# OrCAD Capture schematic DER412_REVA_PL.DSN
size C; title: 120V / 100mA    A19 application; rev: A; note: <Doc>
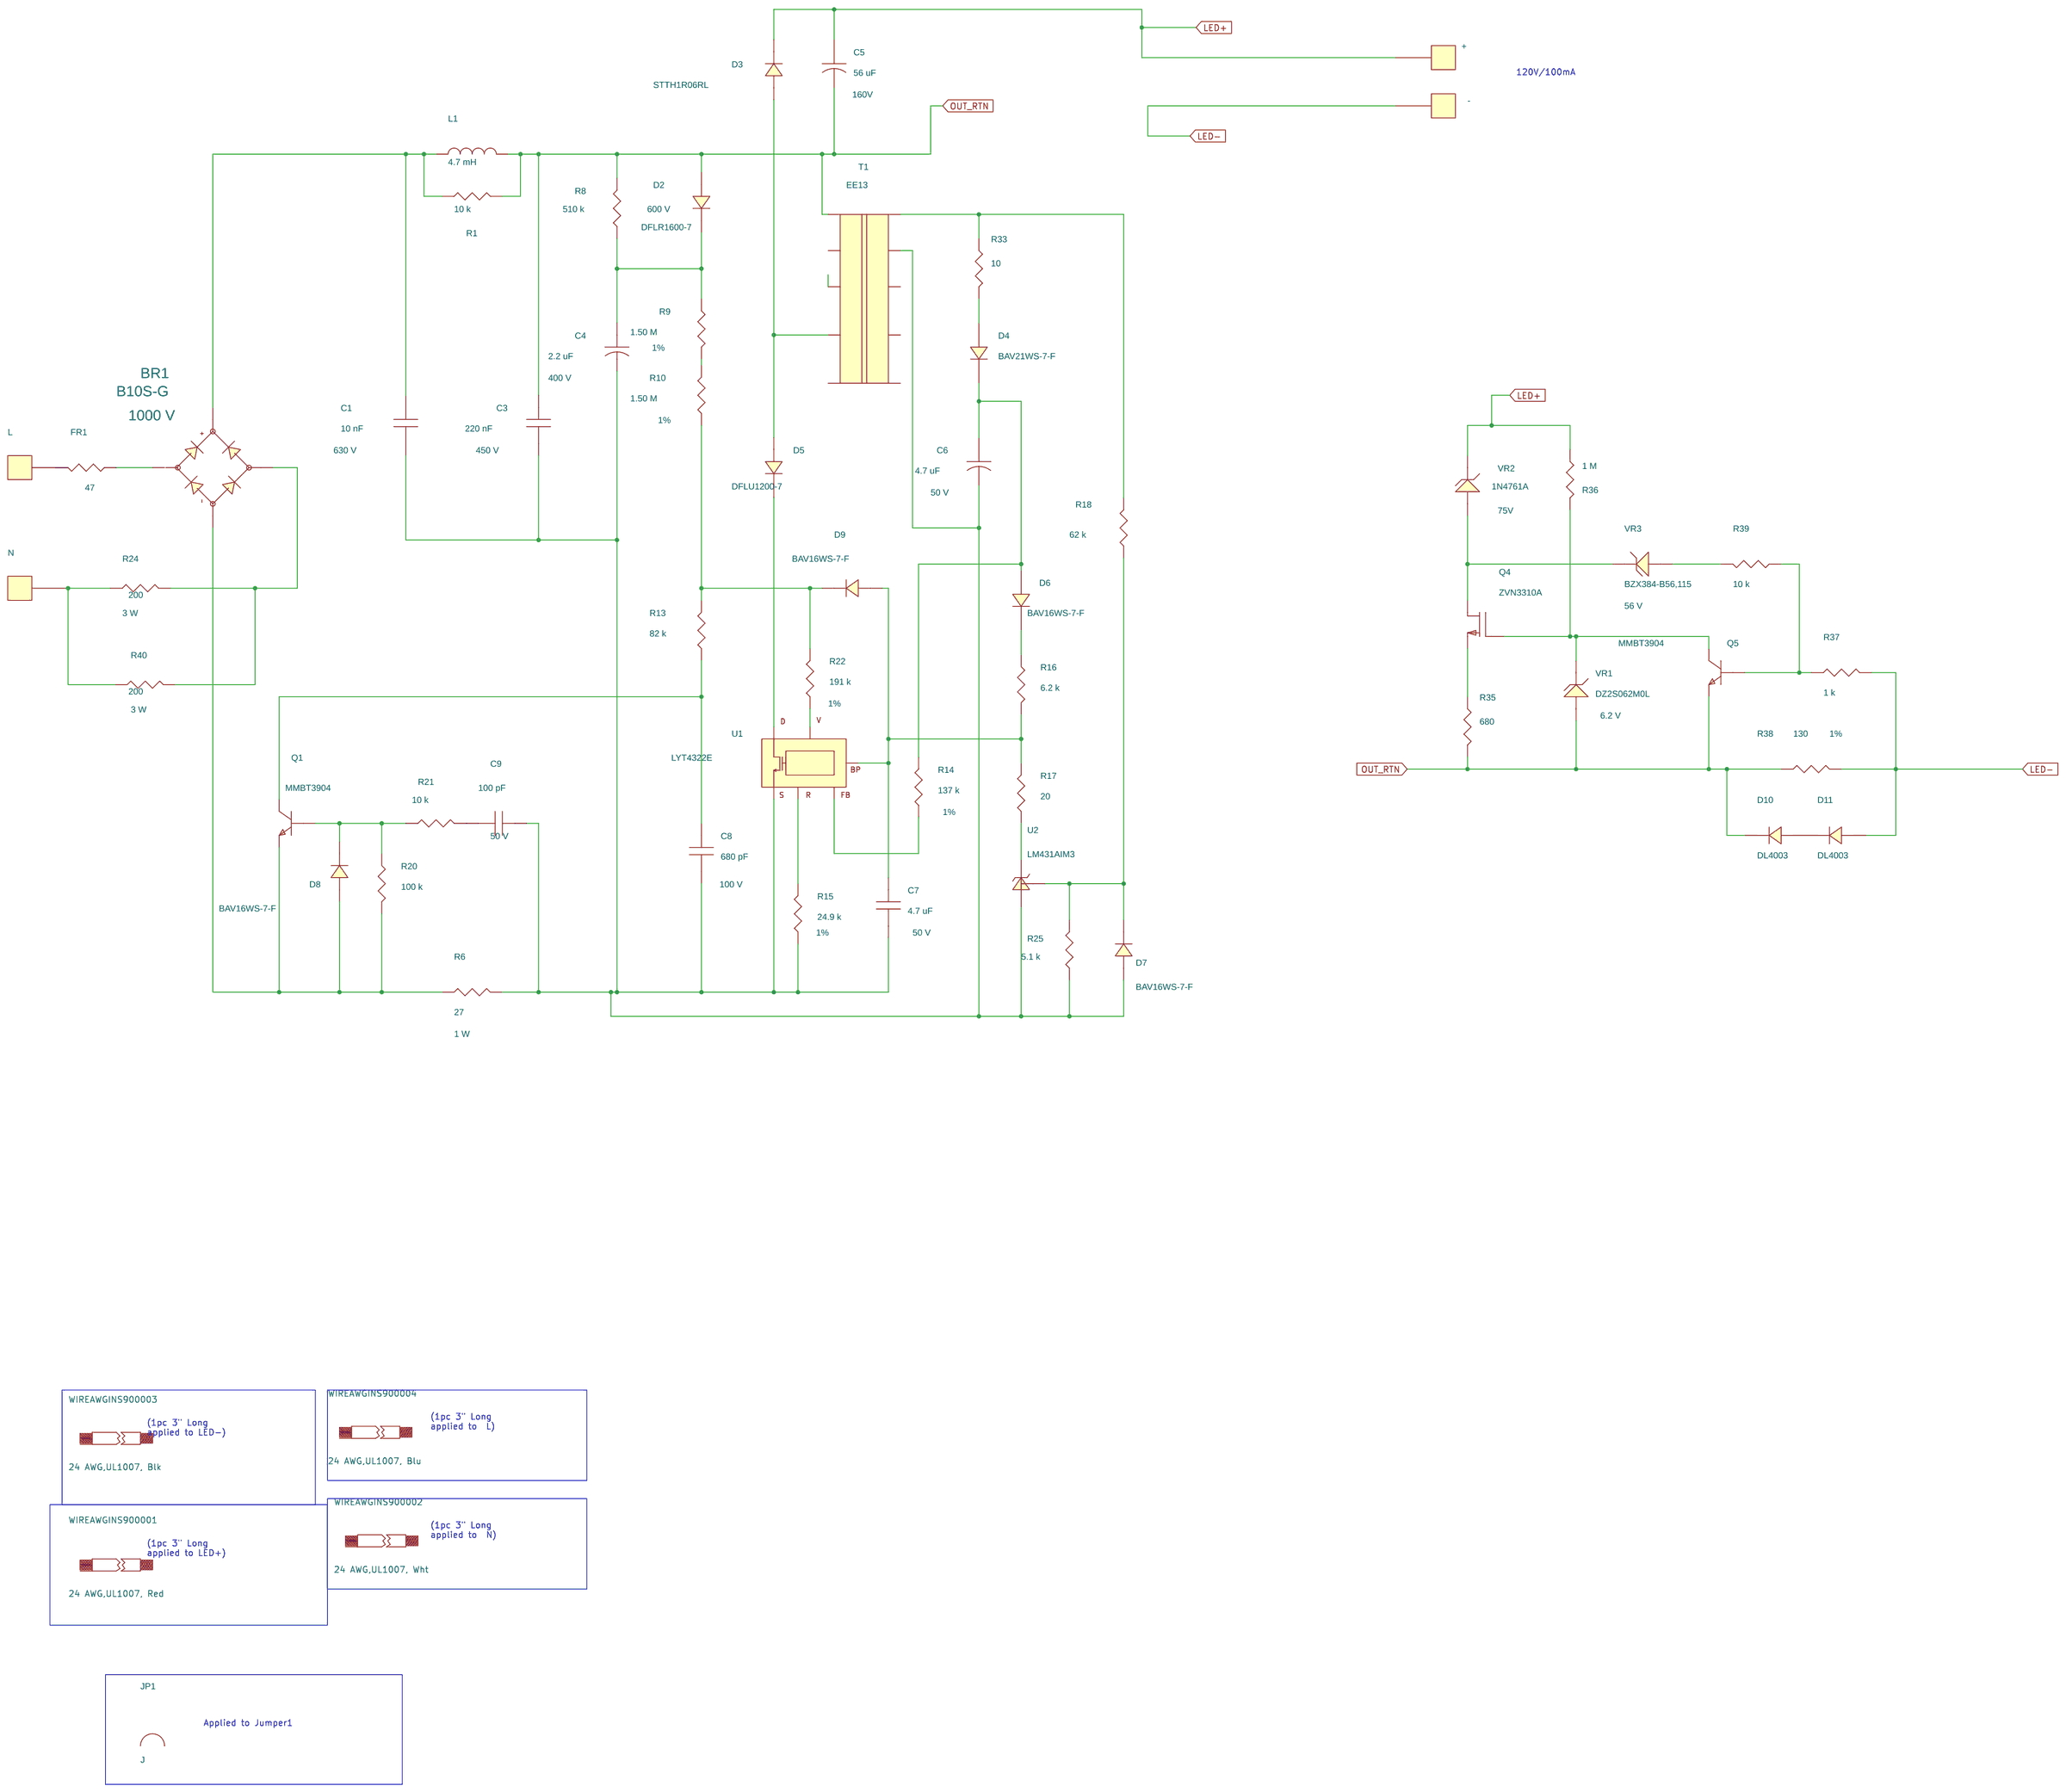
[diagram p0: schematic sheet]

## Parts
+  PCB Terminal 22 AWG  [pi_hole_22awg]
-  PCB Terminal 22 AWG  [pi_hole_22awg]
BR1  B10S-G  [pismsoic4]
C1  10 nF  [pinpcaprad500x200400030]
C3  220 nF  [pi_np_cap_rad470x220ls400d40]
C4  2.2 uF  [pipolcapcyld250ls100030]
C5  56 uF  [pipolcapcyld400ls200040800h]
C6  4.7 uF  [pipolcapclyd200ls80030]
C7  4.7 uF  [pismc0805]
C8  680 pF  [pismc0603]
C9  100 pF  [pismc0603]
D2  DFLR1600-7  [pismddflr120012]
D3  STTH1R06RL  [pidv200x110x040do41]
D4  BAV21WS-7-F  [pismsod323]
D5  DFLU1200-7  [pismddflr120012]
D6  BAV16WS-7-F  [pismsod323]
D7  BAV16WS-7-F  [pismsod323]
D8  BAV16WS-7-F  [pismsod323]
D9  BAV16WS-7-F  [pismsod323]
D10  DL4003  [pismdmll4112]
D11  DL4003  [pismdmll4112]
FR1  47  [PI_2W_VRES240LS200D040]
JP1  J  [pi_jumper400]
L  PCB Terminal 22 AWG  [pi_hole_22awg]
L1  4.7 mH  [pi12wvresd180ls150d040]
N  PCB Terminal 22 AWG  [pi_hole_22awg]
Q1  MMBT3904  [pismsot23132]
Q4  ZVN3310A  [PITO92R100]
Q5  MMBT3904  [pismsot23132]
R1  10 k  [pismr0805]
R6  27  [pi1wresd200ls725d040]
R8  510 k  [pismr1206]
R9  1.50 M  [pismr1206]
R10  1.50 M  [pismr1206]
R13  82 k  [pismr0603]
R14  137 k  [pismr0805]
R15  24.9 k  [pismr0805]
R16  6.2 k  [pismr0805]
R17  20  [pismr1206]
R18  62 k  [pismr0805]
R20  100 k  [pismr0603]
R21  10 k  [pismr0603]
R22  191 k  [pismr0603]
R24  200  [pi2wresd200ls725d040]
R25  5.1 k  [pismr0805]
R33  10  [pismr0805]
R35  680  [pismr0603]
R36  1 M  [pi14wresd100ls400d030]
R37  1 k  [pismr0805]
R38  130  [pismr1206]
R39  10 k  [pismr0805]
R40  200  [pi2wresd200ls725d040]
T1  EE13  [pi_bobbin_ee13v_10p]
U1  LYT4322E  [piicesip76th]
U2  LM431AIM3  [pismsot23123]
VR1  DZ2S062M0L  [pi_sm_d_ssmini2p]
VR2  1N4761A  [pidv200x110x040do41]
VR3  BZX384-B56,115  [pismsod323]
WIRE 24AWG INS?#1  24 AWG,UL1007, Red
WIRE 24AWG INS?#2  24 AWG,UL1007, Wht
WIRE 24AWG INS?#3  24 AWG,UL1007, Blk
WIRE 24AWG INS?#4  24 AWG,UL1007, Blu

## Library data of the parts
+ - L N = TERM_1Pin: Part Number: 35-00008-00
BR1 = DIODE_BRIDGE_~~+-: ALT_SYMBOLS: pi_sm_soic4_slot; Disp_Voltage: 1000 V; Part Number: 15-00818-00; ROOM: 1
C1 = CAP_NP: Disp_Voltage: 630 V; Part Number: 20-00362-00; Voltage: 630 V
C3 = CAP_NP: Disp_Voltage: 450 V; Part Number: 20-08691-00; Voltage: 450 V
C4 = CAP_POL: ALT_SYMBOLS: pipolcapcyld250ls100030h; Disp_Voltage: 400 V; Part Number: 20-01008-00; Voltage: 400 V
C5 = CAP_POL: Disp_Voltage: 160V; FPLIST: pipolcapcyld400ls200040,pipolcapcyld400ls200040800h; Part Number: 20-08761-00; Voltage: 160 V
C6 = CAP_POL: ALT_SYMBOLS: pipolcapclyd200ls80030h; Disp_Voltage: 50 V; FPLIST: pipolcapclyd200ls80030,pipolcapclyd200ls80030h; Part Number: 20-00442-00; Voltage: 50 V
C7 = CAP_NP: Disp_Voltage: 50 V; Part Number: 20-01130-00; Voltage: 50 V
C8 = CAP_NP: Disp_Voltage: 100 V; Part Number: 20-08597-00; Voltage: 100 V
C9 = CAP_NP: Disp_Voltage: 50 V; Part Number: 20-01025-00; Voltage: 50 V
D2 = DIODE: Disp_Voltage: 600 V; Part Number: 15-00826-00
D3 = DIODE: ALT_SYMBOLS: pidax475x125040do41,pidax390x125040do41; FPLIST: pidv200x110x040do41,pidax475x125040do41,pidax390x125040do41; Part Number: 15-01031-00
D4 = DIODE: Part Number: 15-00385-00
D5 = DIODE: Part Number: 15-01043-00
D6-D9 = DIODE: Part Number: 15-00850-00
D10 D11 = DIODE: Part Number: 15-00702-00
FR1 = R: ALT_SYMBOLS: PI_2W_RES240LS500D040,pi_2w_resd145ls455d040; Disp_Power: 2 W; FPLIST: PI_2W_VRES240LS200D040,PI_2W_RES240LS500D040,pi_2w_resd145ls455d040; PCB Editor PCBFP: pi12wvresd180ls150d040,pi12wvresd180ls200d040,pi12wvresd180ls250d040,pi12wresd180ls675d040; Part Number: 05-05559-00; Tol: 5%
JP1 = JUMPER_1: Part Number: 65-00121-00
L1 = INDUCTOR: FPLIST: pi12wresd180ls675d040,pi12wvresd180ls150d040,pi12wvresd180ls200d040,pi12wvresd180ls250d040; Part Number: 30-00126-00
Q1 Q5 = NPN_BEC: Part Number: 55-00048-00
Q4 = FET_N_SGD: FPLIST: PITO92R100,PIT092100; Part Number: 50-00095-00
R1 = R: Part Number: 05-01543-00; ROOM: 1
R6 = R: ALT_SYMBOLS: pi1wvresd120ls200d040,pi1wvresd120ls300d040,pi1wvresd200ls200d040,pi1wvresd200ls300d040,pi1wvresd200ls350d040; Disp_Power: 1 W; FPLIST: pi1wresd200ls725d040,pi1wvresd120ls200d040,pi1wvresd120ls300d040,pi1wvresd200ls200d040,pi1wvresd200ls300d040,pi1wvresd200ls350d040; Part Number: 05-02814-00
R8 = R: Part Number: 05-01417-00
R9 R10 = R: Disp_Tol: 1%; Part Number: 05-03153-00
R13 = R: Part Number: 05-01734-00
R14 = R: Disp_Tol: 1%; Part Number: 05-00793-00
R15 = R: Disp_Tol: 1%; Part Number: 05-00722-00
R16 = R: Part Number: 05-01538-00
R17 = R: Part Number: 05-01311-00
R18 = R: Part Number: 05-01562-00
R20 = R: Part Number: 05-01736-00
R21 = R: Part Number: 05-01712-00
R22 = R: Disp_Tol: 1%; Part Number: 05-01201-00
R24 R40 = R: ALT_SYMBOLS: pi2wresd200ls900d040,pi2wvresd200ls300d040,pi2wvresd200ls400d040,pi2wresd200ls725d040; Disp_Power: 3 W; FPLIST: pi_3w_vres205ls200d040,pi2wresd200ls900d040,pi2wvresd200ls300d040,pi2wvresd200ls400d040,pi2wresd200ls725d040; Part Number: 05-05405-00
R25 = R: Part Number: 05-01536-00
R33 = R: Part Number: 05-01471-00
R35 = R: Part Number: 05-01684-00
R36 = R: ALT_SYMBOLS: pi14wvresd100ls200d030,pi14wresd100ls400d030,pi14wresd100ls500d030; FPLIST: pi14wvresd100ls100d030,pi14wvresd100ls200d030,pi14wresd100ls400d030,pi14wresd100ls500d030; Part Number: 05-03103-00
R37 = R: Part Number: 05-01519-00
R38 = R: Disp_Tol: 1%; Part Number: 05-00108-00
R39 = R: Part Number: 05-01543-00
T1 = BEE13_10PINS_GENERIC: Part Number: 25-01023-00
U1 = LNK40X_eSIP: Part Number: 10-00730-00
U2 = TL431_SOT-23_CAR: Part Number: 45-00268-00
VR1 = DIODE_ZENER: Disp_Voltage: 6.2 V; Part Number: 15-01005-00
VR2 = DIODE_ZENER: ALT_SYMBOLS: pidax475x125040do41,pidv200x110x040do41wbead,pidax390x125040do41; Disp_Voltage: 75V; FPLIST: pidv200x110x040do41,pidax475x125040do41,pidv200x110x040do41wbead,pidax390x125040do41; Part Number: 15-00631-00
VR3 = DIODE_ZENER: Disp_Voltage: 56 V; Part Number: 15-00921-00
WIRE 24AWG INS?#1 = Wire_24AWG_Ins: Part Number: 66-00137-00
WIRE 24AWG INS?#2 = Wire_24AWG_Ins: Part Number: 66-00136-00
WIRE 24AWG INS?#3 = Wire_24AWG_Ins: Part Number: 66-00134-00
WIRE 24AWG INS?#4 = Wire_24AWG_Ins: Part Number: 66-00135-00

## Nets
LED+: +.1 C5.1 D3.1 R36.2 VR2.1
LED-: -.1 D11.2 R37.2 R38.2
OUT_RTN: C3.1 C5.2 D2.2 D10.1 L1.2 Q5.2(EMITTER) R1.2 R8.1 R35.2 R38.1 T1.1 VR1.2
N1678526: C1.2 C3.2 C4.2 C6.2 C7.2 C8.2 C9.1 D7.2 R6.1 R15.1 R25.1 T1.9 U1.5(S) U2.2(A)
N2200496: C4.1 D2.1 R8.2 R9.1
N2229506: BR1.4 D8.2 Q1.2(EMITTER) R6.2 R20.2
N2302506: FR1.2 L.1
N2491459: C7.1 D9.2 R16.2 R17.2 U1.4(BP)
N2492720: D5.1 U1.7(D)
N2492766: R15.2 U1.1(R)
N2532048: R14.1 U1.3(FB)
N2536376: BR1.1 R24.2 R40.1
N2538393: BR1.3 C1.1 L1.1 R1.1
N3711440: D3.2 D5.2 T1.4
N3740281: R22.1 U1.2(V)
N3830550: C6.1 D4.1 D6.2 R14.2
N3837669: R9.2 R10.1
N3895372: C8.1 Q1.3(COLLECTOR) R13.2
N3895502: D8.1 Q1.1(BASE) R20.1 R21.2
N3896990: D9.1 R10.2 R13.1 R22.2
N3918631: D7.1 R18.1 R25.2 U2.3(VREF)
N3918661: R17.1 U2.1(C)
N3918954: R18.2 R33.1 T1.10
N3939020: D6.1 R16.1
N3949879: D4.2 R33.2
N3952070: BR1.2 FR1.1
N3964753: Q4.2(G) Q5.3(COLLECTOR) R36.1 VR1.1
N3964758: Q4.1(S) R35.1
N3964791: Q4.3(D) VR2.2 VR3.1
N3965058: Q5.1(BASE) R37.1 R39.1
N3965494: R39.2 VR3.2
N3967550: N.1 R24.1 R40.2
N3975755: C9.2 R21.1
N3978327: D10.2 D11.1

Not connected (* = marked no-connect by the designer): JP1 1 2; T1 2 3 5 6 7 8

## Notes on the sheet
- 120V/100mA
- (1pc 3" Long
  applied to LED-)
- (1pc 3" Long
  applied to  L)
- (1pc 3" Long
  applied to  N)
- (1pc 3" Long
  applied to LED+)
- Applied to Jumper1
